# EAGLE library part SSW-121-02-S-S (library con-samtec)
THROUGH-HOLE .025" SQ POST SOCKET Source: Samtec SSW.pdf
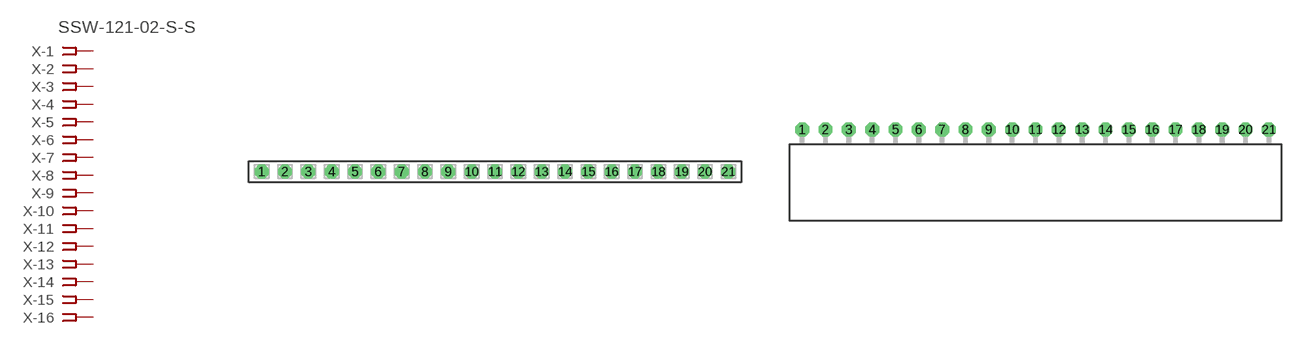
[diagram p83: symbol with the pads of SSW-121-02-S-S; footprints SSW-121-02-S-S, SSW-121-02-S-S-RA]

Designator prefix X; gates -1=FPINV -2=FPIN -3=FPIN -4=FPIN -5=FPIN -6=FPIN -7=FPIN -8=FPIN -9=FPIN -10=FPIN -11=FPIN -12=FPIN -13=FPIN -14=FPIN -15=FPIN -16=FPIN -17=FPIN -18=FPIN -19=FPIN -20=FPIN -21=FPIN

## SSW-121-02-S-S (MPN: SSW-121-02-S-S; OC_FARNELL: unknown; OC_NEWARK: 11P9658)  [SSW-121-02-S-S]
1  -1:1  pas
2  -2:1  pas
3  -3:1  pas
4  -4:1  pas
5  -5:1  pas
6  -6:1  pas
7  -7:1  pas
8  -8:1  pas
9  -9:1  pas
10  -10:1  pas
11  -11:1  pas
12  -12:1  pas
13  -13:1  pas
14  -14:1  pas
15  -15:1  pas
16  -16:1  pas
17  -17:1  pas
18  -18:1  pas
19  -19:1  pas
20  -20:1  pas
21  -21:1  pas

## SSW-121-02-S-S-RA (MPN: SSW-121-02-S-S-RA; OC_FARNELL: unknown; OC_NEWARK: 11P9659)  [SSW-121-02-S-S-RA]
Pads as for SSW-121-02-S-S

## Footprint SSW-121-02-S-S (pad centres in mm)
THROUGH-HOLE .025" SQ POST SOCKET Source: Samtec SSW.pdf
drill 1 pad 1.5 octagon: 1 -25.4,0; 2 -22.86,0; 3 -20.32,0; 4 -17.78,0; 5 -15.24,0; 6 -12.7,0; 7 -10.16,0; 8 -7.62,0; 9 -5.08,0; 10 -2.54,0; 11 0,0; 12 2.54,0; 13 5.08,0; 14 7.62,0; 15 10.16,0; 16 12.7,0; 17 15.24,0; 18 17.78,0; 19 20.32,0; 20 22.86,0; 21 25.4,0

## Footprint SSW-121-02-S-S-RA (pad centres in mm)
THROUGH-HOLE .025" SQ POST SOCKET Source: Samtec SSW.pdf
drill 1 pad 1.5 octagon: 1 -25.4,1.524; 2 -22.86,1.524; 3 -20.32,1.524; 4 -17.78,1.524; 5 -15.24,1.524; 6 -12.7,1.524; 7 -10.16,1.524; 8 -7.62,1.524; 9 -5.08,1.524; 10 -2.54,1.524; 11 0,1.524; 12 2.54,1.524; 13 5.08,1.524; 14 7.62,1.524; 15 10.16,1.524; 16 12.7,1.524; 17 15.24,1.524; 18 17.78,1.524; 19 20.32,1.524; 20 22.86,1.524; 21 25.4,1.524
